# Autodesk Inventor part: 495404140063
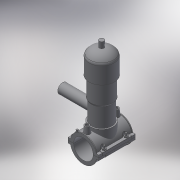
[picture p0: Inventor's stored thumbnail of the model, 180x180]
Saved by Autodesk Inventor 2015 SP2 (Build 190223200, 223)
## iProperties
Created: 2017-07
Part Number: 495404140063
Material: Generic
Description: PLASSON TAPPING VALVE 140-63
Document SubType Name: Modeling
Designer: KIM
Density: 1 g/cm^3
Appearance: Default
Author: KIM
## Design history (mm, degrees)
derived "495404-4954S4.ipt"
feature "Solid1::495404-4954S4.ipt"
feature "Solid2::495404-4954S4.ipt"
tag "TaggingFeature1"
body "Solid1"
body "Solid2"
other parameters: "d3" = 35, "d4" = 118, "d5" = 0, "d6" = 0.1, "d8" = 0, "d19" = 6, "d20" = 6, "d21" = 70.8, "d23" = 0, "d24" = 35.4, "d26" = 0, "d27" = 3, "d28" = 3, "d29" = 3, "d30" = 46.66667, "d31" = 6, "d32" = 0, "d33" = 0, "d34" = 0.6, "d40" = 87.36, "d47" = 135, "d70" = 15, "d72" = 0, "d73" = 6, "d75" = 5, "d76" = 0, "d77" = 7, "d79" = 15, "d80" = 47.2, "d82" = 5 deg, "d84" = 4, "d85" = 14, "d86" = 0, "d87" = 3, "d88" = 0, "d89" = 1, "d90" = 1, "d91" = 94.4, "d92" = 0, "d93" = 0.5, "d94" = 73.68421, "d96" = 173.04, "d97" = 2.36, "d98" = 0, "d120" = 140 deg, "d121" = 24.228, "d122" = 20 deg, "d123" = 336, "d124" = 100.8, "d126" = 0, "d143" = 144.2, "d145" = 21.53846, "d149" = 2.1, "d150" = 23.69231, "d153" = 118, "d154" = 0, "d156" = 84, "d157" = 160 deg, "d159" = 5.6, "d161" = 2.1, "d162" = 70.8, "d163" = 0, "d167" = 14, "d168" = 81.95122, "d170" = 3, "d172" = 0, "d173" = 1, "d176" = 20 deg, "d177" = 9.8, "d178" = 28, "d180" = 0, "d183" = 11.2, "d184" = 7.84, "d185" = 38.35, "d186" = 38.35, "d187" = 84, "d188" = 8.4, "d189" = 9.8, "d190" = 0, "d191" = 126, "d193" = 6.8, "d194" = 2.95, "d195" = 90 deg, "d197" = 0, "d199" = 0, "d205" = 14.64, "d206" = 81.33333, "d207" = 244, "d208" = 224.48, "d209" = 207.4, "d210" = 200.08, "d211" = 146.4, "d212" = 85.4, "d213" = 65.88, "d214" = 73.2, "d216" = 19.52, "d217" = 70.76, "d218" = 80.52, "d222" = 0, "d223" = 168, "d224" = 186, "d225" = 51, "d226" = 63, "d229" = 186, "d230" = 0, "H_" = 186, "L_" = 118, "d_t" = 6, "d_1" = 63, "H_1" = 51, "H_2" = 244, "d148" = 2.1, "d160" = 2.1, "d169" = 3, "d192" = 6.8, "d228" = 50.4
